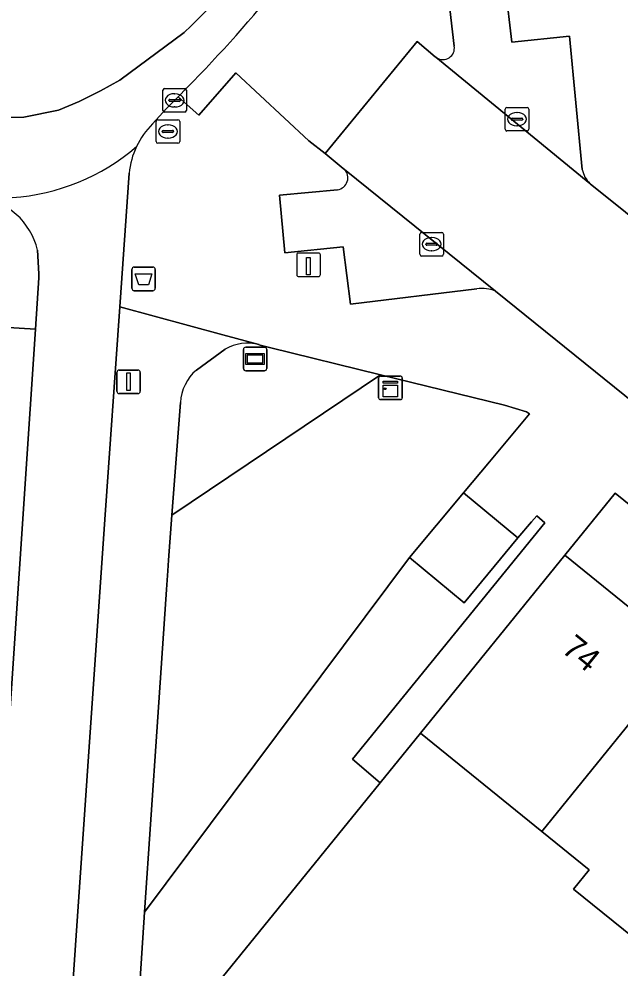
# Model space of a CAD drawing. Extents: x 160157 to 160921, y 381516 to 382045.
# Drawn here: x 160533.27 to 160558.75, y 381683.37 to 381723.64 of the extents above; entities that cross this region are included whole.
import ezdxf

# ---------------------------------------------------------------- set-up
doc = ezdxf.new("R2010")
doc.units = 0
for name, color, linetype in [('IMGEO_Afvalbak', 7, 'Continuous'), ('IMGEO_Berm_groen', 7, 'Continuous'), ('IMGEO_Erf', 7, 'Continuous'), ('IMGEO_Fietspad_gesloten', 7, 'Continuous'), ('IMGEO_Groenvoorziening', 7, 'Continuous'), ('IMGEO_Informatiebord', 7, 'Continuous'), ('IMGEO_Kast', 7, 'Continuous'), ('IMGEO_Kolk', 7, 'Continuous'), ('IMGEO_Laadpaal', 7, 'Continuous'), ('IMGEO_Lage_trafo', 7, 'Continuous'), ('IMGEO_Lichtmast', 7, 'Continuous'), ('IMGEO_Pand', 7, 'Continuous'), ('IMGEO_Pand_nummerreeks', 7, 'Continuous'), ('IMGEO_Parkeervlak_open', 7, 'Continuous'), ('IMGEO_Rijbaan_lokaal_gesloten', 7, 'Continuous'), ('IMGEO_Rijbaan_lokaal_open', 7, 'Continuous'), ('IMGEO_Rioolput', 7, 'Continuous'), ('IMGEO_Voetpad_open', 7, 'Continuous')]:
    doc.layers.add(name, color=color, linetype=linetype)

msp = doc.modelspace()

# ---------------------------------------------------------------- linework, layer by layer
at = {"layer": 'IMGEO_Afvalbak'}
for p, q in [((160538.157, 381713.109), (160538.947, 381713.109)), ((160538.947, 381713.109), (160538.157, 381713.109)), ((160538.057, 381712.209), (160538.057, 381713.009)), ((160538.057, 381713.009), (160538.057, 381712.209)), ((160539.047, 381713.009), (160539.047, 381712.209)), ((160539.047, 381712.209), (160539.047, 381713.009)), ((160538.947, 381712.109), (160538.157, 381712.109)), ((160538.157, 381712.109), (160538.947, 381712.109))]:
    msp.add_line(p, q, dxfattribs=at)
msp.add_lwpolyline([(160538.2, 381712.823), (160538.904, 381712.823), (160538.755, 381712.353), (160538.349, 381712.353), (160538.2, 381712.823)], dxfattribs=at)
for centre, start, end in [((160538.157, 381713.009), 90, 180), ((160538.157, 381713.009), 90, 180), ((160538.947, 381713.009), 0, 90), ((160538.947, 381713.009), 360, 90), ((160538.157, 381712.209), 180, 270), ((160538.157, 381712.209), 180, 270), ((160538.947, 381712.209), 270, 0), ((160538.947, 381712.209), 270, 0)]:
    msp.add_arc(centre, 0.1, start, end, dxfattribs=at)
at = {"layer": 'IMGEO_Berm_groen'}
msp.add_lwpolyline([(160531.229, 381668.639), (160531.665, 381676.173), (160533.971, 381710.473), (160531.412, 381710.633), (160531.562, 381713.83)], dxfattribs=at)
at = {"layer": 'IMGEO_Erf'}
msp.add_lwpolyline([(160558.545, 381703.514), (160556.409, 381700.887), (160561.559, 381696.713), (160566.569, 381692.651), (160571.58, 381688.589), (160576.591, 381684.528), (160581.601, 381680.467), (160586.612, 381676.405), (160591.761, 381672.231), (160587.997, 381667.587), (160590.45, 381665.598), (160595.868, 381673.258), (160595.937, 381673.356), (160593.737, 381675.072)], close=True, dxfattribs=at)
msp.add_lwpolyline([(160565.474, 381681.531), (160562.708, 381683.773), (160562.362, 381683.347), (160560.35, 381684.978), (160560.265, 381685.047), (160559.698, 381684.347), (160556.78, 381686.711), (160557.449, 381687.535), (160555.44, 381689.163), (160550.289, 381693.337), (160548.581, 381691.23), (160538.354, 381678.613)], dxfattribs=at)
at = {"layer": 'IMGEO_Fietspad_gesloten'}
for points in [[(160536.908, 381702.404), (160537.542, 381711.422), (160537.941, 381717.089)], [(160534.052, 381713.831), (160534.111, 381712.822), (160534.118, 381712.658), (160533.971, 381710.473), (160531.665, 381676.173), (160531.229, 381668.639)], [(160535.403, 381680.442), (160536.908, 381702.404)]]:
    msp.add_lwpolyline(points, dxfattribs=at)
for centre, radius, start, end in [((160532.389, 381725.023), 8.98, 273.7757, 310.7646), ((160541.315, 381716.772), 3.389, 154.6678, 174.6338), ((160531.18, 381713.155), 2.951, 13.2468, 82.7307)]:
    msp.add_arc(centre, radius, start, end, dxfattribs=at)
at = {"layer": 'IMGEO_Groenvoorziening'}
for points in [[(160542.007, 381709.626), (160540.791, 381708.742)], [(160548.601, 381708.54), (160543.894, 381709.696), (160543.445, 381709.818)], [(160540.118, 381707.359), (160539.755, 381702.59), (160548.601, 381708.54)]]:
    msp.add_lwpolyline(points, dxfattribs=at)
for points in [[(160549.832, 381700.788), (160552.116, 381703.534), (160553.214, 381704.852), (160554.92, 381706.877), (160554.79, 381706.968), (160553.856, 381707.249), (160548.601, 381708.54), (160539.755, 381702.59), (160539.61, 381700.681), (160539.575, 381700.225), (160539.521, 381699.433), (160539.125, 381693.597), (160538.587, 381685.734)], [(160547.405, 381692.23), (160555.563, 381702.257), (160555.219, 381702.559), (160555.004, 381702.305), (160554.421, 381701.617), (160552.137, 381698.871), (160549.832, 381700.788), (160538.587, 381685.734), (160538.139, 381678.786), (160538.354, 381678.613), (160548.581, 381691.23)]]:
    msp.add_lwpolyline(points, close=True, dxfattribs=at)
for centre, radius, start, end in [((160542.958, 381707.986), 1.896, 75.1097, 120.1005), ((160542.075, 381707.262), 1.96, 130.9444, 177.1583)]:
    msp.add_arc(centre, radius, start, end, dxfattribs=at)
at = {"layer": 'IMGEO_Informatiebord'}
for p, q in [((160542.782, 381708.812), (160542.782, 381709.612)), ((160542.782, 381709.612), (160542.782, 381708.812)), ((160542.882, 381709.712), (160543.672, 381709.712)), ((160543.672, 381709.712), (160542.882, 381709.712)), ((160543.772, 381709.612), (160543.772, 381708.812)), ((160543.772, 381708.812), (160543.772, 381709.612)), ((160543.672, 381708.712), (160542.882, 381708.712)), ((160542.882, 381708.712), (160543.672, 381708.712))]:
    msp.add_line(p, q, dxfattribs=at)
for points in [[(160542.883, 381709.444), (160543.671, 381709.444), (160543.671, 381708.98), (160542.883, 381708.98), (160542.883, 381709.444)], [(160542.948, 381709.379), (160542.948, 381709.045), (160543.606, 381709.045), (160543.606, 381709.379), (160542.948, 381709.379)]]:
    msp.add_lwpolyline(points, dxfattribs=at)
for centre, start, end in [((160542.882, 381709.612), 90, 180), ((160542.882, 381709.612), 90, 180), ((160543.672, 381709.612), 0, 90), ((160543.672, 381709.612), 360, 90), ((160542.882, 381708.812), 180, 270), ((160542.882, 381708.812), 180, 270), ((160543.672, 381708.812), 270, 0), ((160543.672, 381708.812), 270, 0)]:
    msp.add_arc(centre, 0.1, start, end, dxfattribs=at)
at = {"layer": 'IMGEO_Kast'}
for p, q in [((160548.518, 381707.56), (160548.518, 381708.401)), ((160548.518, 381708.401), (160548.518, 381707.56)), ((160548.593, 381708.485), (160549.434, 381708.485)), ((160549.434, 381708.485), (160548.593, 381708.485)), ((160549.518, 381708.41), (160549.518, 381707.569)), ((160549.518, 381707.569), (160549.518, 381708.41)), ((160549.443, 381707.485), (160548.602, 381707.485)), ((160548.602, 381707.485), (160549.443, 381707.485))]:
    msp.add_line(p, q, dxfattribs=at)
for points in [[(160548.713, 381708.275), (160549.313, 381708.275), (160549.313, 381708.19), (160548.713, 381708.19), (160548.713, 381708.275)], [(160548.713, 381708.1), (160549.313, 381708.1), (160549.313, 381707.611), (160548.713, 381707.611), (160548.713, 381708.1)]]:
    msp.add_lwpolyline(points, dxfattribs=at)
msp.add_circle((160548.797, 381707.949), 0.0377, dxfattribs=at)
for centre, start, end in [((160548.596, 381708.407), 92.4484, 184.2845), ((160548.596, 381708.407), 92.4484, 184.2845), ((160549.44, 381708.407), 2.4484, 94.2845), ((160549.44, 381708.407), 2.4484, 94.2845), ((160548.596, 381707.563), 182.4484, 274.2845), ((160548.596, 381707.563), 182.4484, 274.2845), ((160549.44, 381707.563), 272.4484, 4.2845), ((160549.44, 381707.563), 272.4484, 4.2845)]:
    msp.add_arc(centre, 0.0779, start, end, dxfattribs=at)
at = {"layer": 'IMGEO_Kolk'}
for p, q in [((160539.368, 381719.758), (160539.368, 381720.61)), ((160539.443, 381720.684), (160540.295, 381720.684)), ((160539.856, 381720.464), (160539.881, 381720.464)), ((160540.369, 381720.61), (160540.369, 381719.758)), ((160539.627, 381720.178), (160539.627, 381720.19)), ((160540.065, 381720.141), (160539.667, 381720.141)), ((160539.67, 381720.227), (160540.068, 381720.227)), ((160540.111, 381720.19), (160540.111, 381720.178)), ((160540.295, 381719.684), (160539.443, 381719.684)), ((160539.879, 381719.904), (160539.854, 381719.904)), ((160553.884, 381718.958), (160553.884, 381719.81)), ((160553.959, 381719.884), (160554.811, 381719.884)), ((160554.372, 381719.664), (160554.397, 381719.664)), ((160554.885, 381719.81), (160554.885, 381718.958)), ((160554.143, 381719.378), (160554.143, 381719.39)), ((160554.581, 381719.341), (160554.183, 381719.341)), ((160554.186, 381719.427), (160554.584, 381719.427)), ((160554.627, 381719.39), (160554.627, 381719.378)), ((160554.811, 381718.884), (160553.959, 381718.884)), ((160554.395, 381719.104), (160554.37, 381719.104)), ((160550.264, 381713.653), (160550.264, 381714.505)), ((160550.339, 381714.579), (160551.191, 381714.579)), ((160550.752, 381714.359), (160550.777, 381714.359)), ((160551.265, 381714.505), (160551.265, 381713.653)), ((160550.523, 381714.073), (160550.523, 381714.085)), ((160550.961, 381714.036), (160550.563, 381714.036)), ((160550.566, 381714.122), (160550.964, 381714.122)), ((160551.007, 381714.085), (160551.007, 381714.073)), ((160551.191, 381713.579), (160550.339, 381713.579)), ((160550.775, 381713.799), (160550.75, 381713.799))]:
    msp.add_line(p, q, dxfattribs=at)
for points in [[(160539.368, 381719.758), (160539.368, 381720.61)], [(160539.443, 381720.684), (160540.295, 381720.684)], [(160540.369, 381720.61), (160540.369, 381719.758)], [(160540.295, 381719.684), (160539.443, 381719.684)], [(160553.884, 381718.958), (160553.884, 381719.81)], [(160553.959, 381719.884), (160554.811, 381719.884)], [(160554.885, 381719.81), (160554.885, 381718.958)], [(160554.811, 381718.884), (160553.959, 381718.884)], [(160550.264, 381713.653), (160550.264, 381714.505)], [(160550.339, 381714.579), (160551.191, 381714.579)], [(160551.265, 381714.505), (160551.265, 381713.653)], [(160551.191, 381713.579), (160550.339, 381713.579)]]:
    msp.add_lwpolyline(points, dxfattribs=at)
for centre, radius, start, end in [((160539.445, 381720.608), 0.0765, 91.552, 178.448), ((160539.445, 381720.608), 0.0765, 91.552, 178.448), ((160540.293, 381720.608), 0.0765, 1.552, 88.448), ((160540.293, 381720.608), 0.0765, 1.552, 88.448), ((160539.667, 381720.187), 0.0403, 85.8775, 175.7526), ((160539.664, 381720.177), 0.0366, 178.938, 274.7102), ((160540.068, 381720.184), 0.043, 264.8664, 352.4533), ((160540.072, 381720.189), 0.0386, 1.7309, 96.639), ((160539.445, 381719.76), 0.0765, 181.552, 268.448), ((160539.445, 381719.76), 0.0765, 181.552, 268.448), ((160540.293, 381719.76), 0.0765, 271.552, 358.448), ((160540.293, 381719.76), 0.0765, 271.552, 358.448), ((160553.961, 381719.808), 0.0765, 91.552, 178.448), ((160553.961, 381719.808), 0.0765, 91.552, 178.448), ((160554.809, 381719.808), 0.0765, 1.552, 88.448), ((160554.809, 381719.808), 0.0765, 1.552, 88.448), ((160554.183, 381719.387), 0.0403, 85.8775, 175.7526), ((160554.18, 381719.377), 0.0366, 178.938, 274.7102), ((160554.584, 381719.384), 0.043, 264.8664, 352.4533), ((160554.588, 381719.389), 0.0386, 1.7309, 96.639), ((160553.961, 381718.96), 0.0765, 181.552, 268.448), ((160553.961, 381718.96), 0.0765, 181.552, 268.448), ((160554.809, 381718.96), 0.0765, 271.552, 358.448), ((160554.809, 381718.96), 0.0765, 271.552, 358.448), ((160550.341, 381714.503), 0.0765, 91.552, 178.448), ((160550.341, 381714.503), 0.0765, 91.552, 178.448), ((160551.189, 381714.503), 0.0765, 1.552, 88.448), ((160551.189, 381714.503), 0.0765, 1.552, 88.448), ((160550.563, 381714.082), 0.0403, 85.8775, 175.7526), ((160550.56, 381714.072), 0.0366, 178.938, 274.7102), ((160550.964, 381714.079), 0.043, 264.8664, 352.4533), ((160550.968, 381714.084), 0.0386, 1.7309, 96.639), ((160550.341, 381713.655), 0.0765, 181.552, 268.448), ((160550.341, 381713.655), 0.0765, 181.552, 268.448), ((160551.189, 381713.655), 0.0765, 271.552, 358.448), ((160551.189, 381713.655), 0.0765, 271.552, 358.448)]:
    msp.add_arc(centre, radius, start, end, dxfattribs=at)
for centre, major_axis, ratio, start_param, end_param in [((160539.855, 381720.184), (-0.387, 0.002), 0.722429, 4.712389, 7.853982), ((160539.88, 381720.184), (-0.39, 0.002), 0.717154, 1.570796, 4.712389), ((160554.371, 381719.384), (-0.387, 0.002), 0.722429, 4.712389, 7.853982), ((160554.396, 381719.384), (-0.39, 0.002), 0.717154, 1.570796, 4.712389), ((160550.751, 381714.079), (-0.387, 0.002), 0.722429, 4.712389, 7.853982), ((160550.776, 381714.079), (-0.39, 0.002), 0.717154, 1.570796, 4.712389)]:
    msp.add_ellipse(centre, major_axis=major_axis, ratio=ratio, start_param=start_param, end_param=end_param, dxfattribs=at)
at = {"layer": 'IMGEO_Laadpaal'}
for p, q in [((160545.046, 381713.623), (160545.046, 381712.782)), ((160545.046, 381713.623), (160545.046, 381712.782)), ((160545.962, 381713.707), (160545.121, 381713.707)), ((160545.962, 381713.707), (160545.121, 381713.707)), ((160546.046, 381712.791), (160546.046, 381713.632)), ((160546.046, 381712.791), (160546.046, 381713.632)), ((160545.13, 381712.707), (160545.971, 381712.707)), ((160545.13, 381712.707), (160545.971, 381712.707))]:
    msp.add_line(p, q, dxfattribs=at)
msp.add_lwpolyline([(160545.461, 381713.52), (160545.621, 381713.52), (160545.621, 381712.787), (160545.461, 381712.787), (160545.461, 381713.52)], dxfattribs=at)
for centre, start, end in [((160545.124, 381713.629), 92.4484, 184.2845), ((160545.124, 381713.629), 92.4484, 184.2845), ((160545.968, 381713.629), 2.4484, 94.2845), ((160545.968, 381713.629), 2.4484, 94.2845), ((160545.124, 381712.785), 182.4484, 274.2845), ((160545.124, 381712.785), 182.4484, 274.2845), ((160545.968, 381712.785), 272.4484, 4.2845), ((160545.968, 381712.785), 272.4484, 4.2845)]:
    msp.add_arc(centre, 0.0779, start, end, dxfattribs=at)
at = {"layer": 'IMGEO_Lage_trafo'}
msp.add_lwpolyline([(160554.421, 381701.617), (160552.116, 381703.534), (160549.832, 381700.788), (160552.137, 381698.871)], close=True, dxfattribs=at)
at = {"layer": 'IMGEO_Lichtmast'}
for p, q in [((160537.519, 381708.742), (160538.309, 381708.742)), ((160538.309, 381708.742), (160537.519, 381708.742)), ((160537.419, 381707.842), (160537.419, 381708.642)), ((160537.419, 381708.642), (160537.419, 381707.842)), ((160538.409, 381708.642), (160538.409, 381707.842)), ((160538.409, 381707.842), (160538.409, 381708.642)), ((160538.309, 381707.742), (160537.519, 381707.742)), ((160537.519, 381707.742), (160538.309, 381707.742))]:
    msp.add_line(p, q, dxfattribs=at)
msp.add_lwpolyline([(160537.839, 381708.617), (160537.989, 381708.617), (160537.989, 381707.867), (160537.839, 381707.867), (160537.839, 381708.617)], dxfattribs=at)
for centre, start, end in [((160537.519, 381708.642), 90, 180), ((160537.519, 381708.642), 90, 180), ((160538.309, 381708.642), 0, 90), ((160538.309, 381708.642), 360, 90), ((160537.519, 381707.842), 180, 270), ((160537.519, 381707.842), 180, 270), ((160538.309, 381707.842), 270, 0), ((160538.309, 381707.842), 270, 0)]:
    msp.add_arc(centre, 0.1, start, end, dxfattribs=at)
at = {"layer": 'IMGEO_Pand'}
for points in [[(160561.559, 381696.713), (160556.409, 381700.887), (160550.289, 381693.337), (160555.44, 381689.163)], [(160566.569, 381692.651), (160561.559, 381696.713), (160555.44, 381689.163), (160557.449, 381687.535), (160556.78, 381686.711), (160559.698, 381684.347), (160560.265, 381685.047), (160560.35, 381684.978)]]:
    msp.add_lwpolyline(points, close=True, dxfattribs=at)
at = {"layer": 'IMGEO_Parkeervlak_open'}
for points in [[(160556.607, 381722.907), (160554.167, 381722.654), (160553.891, 381724.954), (160551.466, 381724.684), (160551.721, 381722.49)], [(160557.151, 381717.248), (160556.607, 381722.907)], [(160550.974, 381721.991), (160550.959, 381722.001), (160550.945, 381722.011), (160557.472, 381716.661)], [(160553.47, 381712.091), (160547.066, 381717.257)], [(160546.779, 381716.393), (160544.312, 381716.156), (160544.536, 381713.72), (160547.01, 381713.967), (160547.318, 381711.543), (160552.686, 381712.188)]]:
    msp.add_lwpolyline(points, dxfattribs=at)
for centre, radius, start, end in [((160551.242, 381722.398), 0.487, 236.5875, 10.8987), ((160546.703, 381716.898), 0.511, 278.5874, 44.6621), ((160558.233, 381717.458), 1.102, 191.0021, 226.3419), ((160552.897, 381710.676), 1.527, 67.9559, 97.938)]:
    msp.add_arc(centre, radius, start, end, dxfattribs=at)
at = {"layer": 'IMGEO_Rijbaan_lokaal_gesloten'}
for points in [[(160540.266, 381723.067), (160537.539, 381721.041), (160536.719, 381720.581), (160535.822, 381720.136), (160534.947, 381719.768), (160533.48, 381719.467), (160532.447, 381719.456)], [(160538.928, 381719.183), (160539.228, 381719.509), (160539.527, 381719.835), (160540.019, 381720.339), (160540.391, 381720.719)]]:
    msp.add_lwpolyline(points, dxfattribs=at)
for centre, radius, start, end in [((160518.343, 381746.652), 32.201, 312.9091, 336.5467), ((160498, 381762.545), 59.552, 315.38401, 321.24578), ((160541.319, 381716.783), 3.388, 134.8901, 154.8622), ((160532.389, 381725.023), 8.98, 273.7757, 310.7646)]:
    msp.add_arc(centre, radius, start, end, dxfattribs=at)
at = {"layer": 'IMGEO_Rijbaan_lokaal_open'}
msp.add_lwpolyline([(160532.447, 381719.456), (160533.48, 381719.467), (160534.947, 381719.768), (160535.822, 381720.136), (160536.719, 381720.581), (160537.539, 381721.041), (160540.266, 381723.067)], dxfattribs=at)
msp.add_lwpolyline([(160568.758, 381707.591), (160557.554, 381716.59), (160557.502, 381716.634), (160557.472, 381716.661), (160550.945, 381722.011), (160550.931, 381722.022), (160550.918, 381722.034), (160550.145, 381722.678), (160546.247, 381717.93), (160547.02, 381717.298), (160547.066, 381717.257), (160553.47, 381712.091), (160558.948, 381707.655), (160565.145, 381702.637), (160577.959, 381692.258), (160593.928, 381679.339), (160594.486, 381678.894), (160598.404, 381683.766), (160597.642, 381684.404), (160592.745, 381688.322), (160581.553, 381697.274)], close=True, dxfattribs=at)
msp.add_arc((160518.343, 381746.652), 32.201, 312.9091, 336.5467, dxfattribs=at)
at = {"layer": 'IMGEO_Rioolput'}
for p, q in [((160539.083, 381718.438), (160539.083, 381719.29)), ((160539.158, 381719.364), (160540.01, 381719.364)), ((160539.571, 381719.144), (160539.596, 381719.144)), ((160540.084, 381719.29), (160540.084, 381718.438)), ((160539.342, 381718.858), (160539.342, 381718.87)), ((160539.78, 381718.821), (160539.382, 381718.821)), ((160539.385, 381718.907), (160539.783, 381718.907)), ((160539.826, 381718.87), (160539.826, 381718.858)), ((160540.01, 381718.364), (160539.158, 381718.364)), ((160539.594, 381718.584), (160539.569, 381718.584))]:
    msp.add_line(p, q, dxfattribs=at)
for points in [[(160539.083, 381718.438), (160539.083, 381719.29)], [(160539.158, 381719.364), (160540.01, 381719.364)], [(160540.084, 381719.29), (160540.084, 381718.438)], [(160540.01, 381718.364), (160539.158, 381718.364)]]:
    msp.add_lwpolyline(points, dxfattribs=at)
for centre, radius, start, end in [((160539.16, 381719.288), 0.0765, 91.552, 178.448), ((160539.16, 381719.288), 0.0765, 91.552, 178.448), ((160540.008, 381719.288), 0.0765, 1.552, 88.448), ((160540.008, 381719.288), 0.0765, 1.552, 88.448), ((160539.382, 381718.867), 0.0403, 85.8775, 175.7526), ((160539.379, 381718.857), 0.0366, 178.938, 274.7102), ((160539.783, 381718.864), 0.043, 264.8664, 352.4533), ((160539.787, 381718.869), 0.0386, 1.7309, 96.639), ((160539.16, 381718.44), 0.0765, 181.552, 268.448), ((160539.16, 381718.44), 0.0765, 181.552, 268.448), ((160540.008, 381718.44), 0.0765, 271.552, 358.448), ((160540.008, 381718.44), 0.0765, 271.552, 358.448)]:
    msp.add_arc(centre, radius, start, end, dxfattribs=at)
for centre, major_axis, ratio, start_param, end_param in [((160539.57, 381718.864), (-0.387, 0.002), 0.722429, 4.712389, 7.853982), ((160539.595, 381718.864), (-0.39, 0.002), 0.717154, 1.570796, 4.712389)]:
    msp.add_ellipse(centre, major_axis=major_axis, ratio=ratio, start_param=start_param, end_param=end_param, dxfattribs=at)
at = {"layer": 'IMGEO_Voetpad_open'}
for points in [[(160551.721, 381722.49), (160551.466, 381724.684), (160553.891, 381724.954), (160554.167, 381722.654), (160556.607, 381722.907), (160557.151, 381717.248)], [(160540.391, 381720.719), (160540.019, 381720.339), (160540.893, 381719.553), (160542.456, 381721.351), (160545.556, 381718.461), (160546.247, 381717.93), (160550.145, 381722.678), (160550.918, 381722.034), (160550.931, 381722.022), (160550.945, 381722.011), (160550.959, 381722.001), (160550.974, 381721.991)], [(160547.066, 381717.257), (160547.02, 381717.298), (160546.247, 381717.93), (160545.556, 381718.461), (160542.456, 381721.351), (160540.893, 381719.553), (160540.019, 381720.339), (160539.527, 381719.835), (160539.228, 381719.509), (160538.928, 381719.183)], [(160537.941, 381717.089), (160537.542, 381711.422), (160541.907, 381710.232), (160543.445, 381709.83), (160543.445, 381709.818), (160543.894, 381709.696), (160548.601, 381708.54), (160553.856, 381707.249), (160554.79, 381706.968), (160554.92, 381706.877), (160553.214, 381704.852), (160552.116, 381703.534), (160554.421, 381701.617), (160555.004, 381702.305), (160555.219, 381702.559), (160555.563, 381702.257), (160547.405, 381692.23), (160548.581, 381691.23), (160550.289, 381693.337), (160556.409, 381700.887), (160558.545, 381703.514), (160593.737, 381675.072)], [(160547.01, 381713.967), (160544.536, 381713.72), (160544.312, 381716.156), (160546.779, 381716.393)], [(160557.472, 381716.661), (160557.502, 381716.634), (160557.554, 381716.59), (160568.758, 381707.591), (160581.553, 381697.274), (160592.745, 381688.322), (160597.642, 381684.404), (160598.404, 381683.766), (160598.577, 381683.621)], [(160552.686, 381712.188), (160547.318, 381711.543), (160547.01, 381713.967)], [(160531.562, 381713.83), (160531.412, 381710.633), (160533.971, 381710.473), (160534.118, 381712.658), (160534.111, 381712.822), (160534.052, 381713.831)], [(160593.928, 381679.339), (160577.959, 381692.258), (160565.145, 381702.637), (160558.948, 381707.655), (160553.47, 381712.091)], [(160543.445, 381709.818), (160543.445, 381709.83), (160541.907, 381710.232), (160537.542, 381711.422), (160536.908, 381702.404), (160535.403, 381680.442)], [(160540.791, 381708.742), (160542.007, 381709.626)], [(160539.125, 381693.597), (160539.521, 381699.433), (160539.575, 381700.225), (160539.61, 381700.681), (160539.755, 381702.59), (160540.118, 381707.359)], [(160539.804, 381624.471), (160539.268, 381628.112), (160539.1, 381629.573), (160538.905, 381631.265), (160538.494, 381635.504), (160538.166, 381639.708), (160537.881, 381644.095), (160537.582, 381652.686), (160537.482, 381658.369), (160537.509, 381663.201), (160537.596, 381667.162), (160537.734, 381671.359), (160538.007, 381676.697), (160538.139, 381678.786), (160538.587, 381685.734), (160539.125, 381693.597)]]:
    msp.add_lwpolyline(points, dxfattribs=at)
for centre, radius, start, end in [((160498, 381762.545), 59.552, 315.38401, 321.24578), ((160551.242, 381722.398), 0.487, 236.5875, 10.8987), ((160541.319, 381716.783), 3.388, 134.8901, 154.8622), ((160541.315, 381716.772), 3.389, 154.6678, 174.6338), ((160546.703, 381716.898), 0.511, 278.5874, 44.6621), ((160558.233, 381717.458), 1.102, 191.0021, 226.3419), ((160531.18, 381713.155), 2.951, 13.2468, 82.7307), ((160552.897, 381710.676), 1.527, 67.9559, 97.938), ((160542.958, 381707.986), 1.896, 75.1097, 120.1005), ((160542.075, 381707.262), 1.96, 130.9444, 177.1583)]:
    msp.add_arc(centre, radius, start, end, dxfattribs=at)

# ---------------------------------------------------------------- texts
at = {"layer": 'IMGEO_Pand_nummerreeks'}
msp.add_text('74', height=1, rotation=320.9721, dxfattribs=at).set_placement((160556.227, 381696.812))

doc.saveas('drawing.dxf')
